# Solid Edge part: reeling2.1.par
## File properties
Author: Mac
Template: Normal.par
Last saved by: Mac
Revision: 8
Application: Solid Edge
Material: Stainless steel
Face Style: Steel
Fill Style: ANSI32(Steel)
Virtual Style: Stainless steel
Coef. of Thermal Exp: 1.6e-05
Thermal Conductivity: 17.0
Specific Heat: 502.0
Modulus of Elasticity: 193053196000.0
Poission's Ratio: 0.29
Yield Stress: 310264065.0
Ultimate Stress: 641212401.0
Elongation: 0.0
Density: 7750,000 kg/m^3
Accuracy: 0,990
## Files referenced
..\Asm13.asm
=C:\Documents and Settings\Mac\Desktop\copy of paat2\Asm13.asm
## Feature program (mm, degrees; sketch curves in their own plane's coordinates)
make body feature "unnamed MakeBodyFeature 1"
sketch for "ExtrudedProtrusion_327" plane through (-127.9931, 9.3726, 2.45) normal (0, -0.965977, -0.258629) x-axis (-1, 0, 0)
  circle centre (0, 0) radius 0.8
extrude "ExtrudedProtrusion_327" add finite 0.06 along -normal
pattern "Pattern_3" of "ExtrudedProtrusion_327" along a curve  XDirCount = 6; YDirCount = 6
extrude "unnamed Protrusion 1" add finite 0.06
extrude "unnamed Protrusion 2" add finite 0.06
extrude "unnamed Protrusion 3" add finite 0.06
extrude "unnamed Protrusion 4" add finite 0.06
extrude "unnamed Protrusion 5" add finite 0.06
swept protrusion "SweptProtrusion_7"
sketch for "ExtrudedProtrusion_333" plane through (0, 0, 4.9) normal (0, 0, 1) x-axis (1, 0, 0)
  circle centre (17.9001, -18.3935) radius 0.8
extrude "ExtrudedProtrusion_333" add finite 0.06 along +normal
swept protrusion "SweptProtrusion_8"
swept protrusion "SweptProtrusion_10"
swept protrusion "SweptProtrusion_11"  Profile_48_CrossSections_Plane1_FractionOfCurve = 1
swept protrusion "SweptProtrusion_12"
swept protrusion "SweptProtrusion_13"  Profile_54_CrossSections_Plane1_FractionOfCurve = 1
sketch for "unnamed Cutout 1" plane through (-127.9931, 9.3726, 2.45) normal (0, -0.965977, -0.258629) x-axis (1, 0, 0)
  circle centre (0, 0) radius 0.8
extrude "unnamed Cutout 1" cut through along +normal
pattern "Pattern_4" of "unnamed Cutout 1" along a curve  XDirCount = 6; YDirCount = 6
extrude "unnamed Cutout 2" cut through
extrude "unnamed Cutout 3" cut through
extrude "unnamed Cutout 4" cut through
extrude "unnamed Cutout 5" cut through
extrude "unnamed Cutout 6" cut through
sketch for "unnamed Cutout 7" plane through (17.9001, -18.3935, 4.9) normal (0, 0, -1) x-axis (0, -1, 0)
  circle centre (0, 0) radius 0.8
extrude "unnamed Cutout 7" cut through along +normal
Other named dimensions: "ExtrudedSurface_2": FiniteDepth = 16.4967 mm | "ExtrudedSurface_5": FiniteDepth = 4.6694 mm
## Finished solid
Body 1: sheet body, 1 face, 4 edges, 4 vertices.
  Faces by surface: plane 1
  Edges by curve: line 4
Body 2: solid body, 49 faces, 67 edges, 26 vertices.
  Faces by surface: cylinder 18, plane 18, spline 8, torus 5
  Edges by curve: intersection 33, circle 28, curve on surface 2, ellipse 2, line 2
Body 3: solid body, 6 faces, 5 edges, 0 vertices.
  Faces by surface: spline 4, plane 2
  Edges by curve: circle 5
Body 4: sheet body, 3 faces, 10 edges, 8 vertices.
  Faces by surface: plane 2, cylinder 1
  Edges by curve: line 8, circle 2
Body 5: sheet body, 2 faces, 7 edges, 6 vertices.
  Faces by surface: cylinder 1, swept 1
  Edges by curve: line 3, circle 2, spline 2
Body 6: sheet body, 1 face, 4 edges, 4 vertices.
  Faces by surface: plane 1
  Edges by curve: line 4
Bounding box of the edges (mm; curved faces can reach further): 169.695 x 35.822 x 18.375, from (-130.9931, -20.9503, -0.0467) to (38.7019, 14.872, 18.3277).
Cylindrical faces by radius (mm): R0.1 x11, R0.8 x7, R1.3175 x1, R19.2522 x1
Toroidal faces (ring radius, tube radius in mm): R0.5971 r0.1 x1, R0.6616 r0.1 x1, R0.9337 r0.1 x1, R1.0266 r0.1 x1, R1.2594 r0.1 x1
Planar faces by outward normal: +z 1, -z 1, oblique 18
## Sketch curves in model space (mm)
line (-0.09, -3.0066, 2.45) -> (1.4978, 1.7346, 2.45)
line (-31.5077, 4.1083, 2.45) -> (-30.6909, 9.0411, 2.45)
line (-95.7736, 9.1751, 2.45) -> (-95.6025, 14.1721, 2.45)
line (-63.5548, 7.6517, 2.45) -> (-63.1364, 12.6342, 2.45)
line (-112.6267, 10.582, 9.45) -> (-122.1194, 10.6326, 9.45)
spline (-112.6267, 10.582, 9.45) -> (-12.8988, 2.3419, 9.45) -> (33.2586, -18.3935, 9.45)
line (17.9001, -18.3935, 4.9) -> (36.893, -18.3935, 18.2459)
arc centre (37.617, -18.3935, 17.2155) radius 1.2594 from (38.617, -18.3935, 16.45) through (38.5255, -18.3935, 18.0876) to (36.893, -18.3935, 18.2459)
line (27.9001, -18.3935, 2.45) -> (38.617, -18.3935, 16.45)
line (-127.9931, 10.6079, 2.45) -> (-122.0163, 10.6079, 9.5729)
arc centre (-107.2682, 10.6079, -2.8022) radius 19.2522 from (-107.2682, 10.6079, 16.45) through (-115.4046, 10.6079, 14.6462) to (-122.0163, 10.6079, 9.5729)
line (-107.2682, 10.6079, 16.45) -> (38.617, 10.6079, 16.45)
arc centre (-126.6781, 9.2904, 16.45) radius 1.3175 from (-127.9931, 9.3726, 16.45) through (-127.5838, 10.2473, 16.45) to (-126.6879, 10.6079, 16.45)
spline (-126.6879, 10.6079, 16.45) -> (-13.3924, 3.4404, 16.45) -> (38.617, -18.3935, 16.45)
line (-127.9931, 8.7167, 4.9) -> (-127.9931, 10.0286, 0)
spline (27.9001, -18.3935, 2.45) -> (-35.1568, 4.6521, 2.45) -> (-127.9931, 9.3726, 2.45)
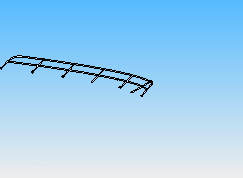
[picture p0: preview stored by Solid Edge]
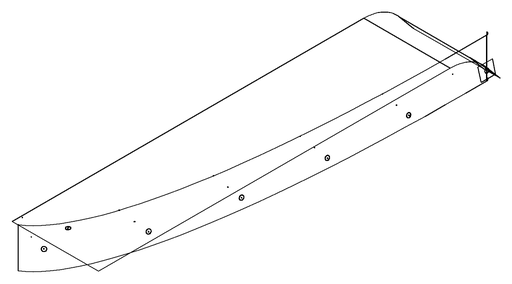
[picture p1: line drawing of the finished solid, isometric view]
